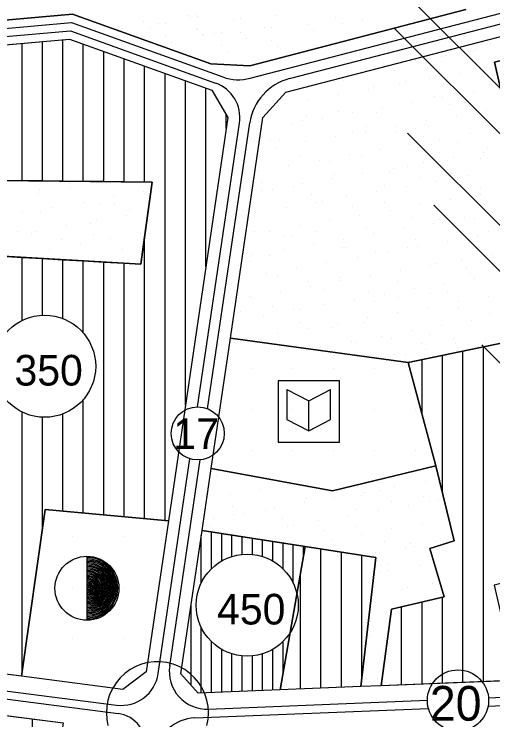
# Model space of a CAD drawing. Extents: x 419109 to 421295, y 4452223 to 4457798.
# Drawn here: x 420565 to 420799.4, y 4454402 to 4454747.5 of the extents above; entities that cross this region are included whole.
import ezdxf

# ---------------------------------------------------------------- set-up
doc = ezdxf.new("R2010")
doc.units = 0
for name, color, linetype in [('ADA', 7, 'Continuous'), ('ADAKENARI', 7, 'Continuous'), ('Default', 7, 'Continuous'), ('KALDIRIM', 7, 'Continuous'), ('KD_DAIRE', 7, 'Continuous'), ('KD_KAV_25', 7, 'Continuous'), ('KD_YGEN', 7, 'Continuous'), ('LJ_SEMBOL', 7, 'Continuous'), ('PL_AYA_PARK_DINLENME', 7, 'Continuous'), ('PL_K_YONETIM', 7, 'Continuous'), ('PL_KON_MEV_350', 7, 'Continuous'), ('PL_KON_MEV_450', 7, 'Continuous'), ('PL_SAY_KULTUR_TESIS', 7, 'Continuous'), ('SM_DAIRE', 7, 'Continuous'), ('SM_TAKS', 7, 'Continuous'), ('SN_TR_SIVILASMA', 7, 'Continuous'), ('TR_KULTURELTESIS', 7, 'Continuous'), ('TR_ORTAYOGUNKONUT', 7, 'Continuous'), ('TR_PARKALANI', 7, 'Continuous'), ('TR_YONETIMMERK', 7, 'Continuous'), ('TR_YUKSEKYOGUNKONUT', 7, 'Continuous')]:
    doc.layers.add(name, color=color, linetype=linetype)

# ---------------------------------------------------------------- blocks, each defined once
blk = doc.blocks.new('POINT_DISPLAY')
at = {"layer": 'Default'}
blk.add_line((0, 0), (0, 0), dxfattribs=at)

msp = doc.modelspace()

# ---------------------------------------------------------------- linework, layer by layer
at = {"layer": 'ADA'}
for p, q in [((420542.58, 4454666.29), (420632.64, 4454665.27)), ((420632.64, 4454665.27), (420627.04, 4454625.07)), ((420627.04, 4454625.07), (420548.18, 4454629.65)), ((420830.2, 4454592), (420757.98, 4454576.9)), ((420757.98, 4454576.9), (420670.89, 4454588.8)), ((420757.98, 4454576.9), (420771.44, 4454526.31)), ((420771.44, 4454526.31), (420720.85, 4454514.07)), ((420771.44, 4454526.31), (420780.42, 4454489.59)), ((420720.85, 4454514.07), (420661.49, 4454525.07)), ((420568.64, 4454423.32), (420580.23, 4454505)), ((420580.23, 4454505), (420640.51, 4454499.42)), ((420657.01, 4454494.75), (420707.55, 4454486.83)), ((420780.42, 4454489.59), (420768.59, 4454485.92)), ((420695.23, 4454416.69), (420707.55, 4454486.83)), ((420707.55, 4454486.83), (420742.07, 4454481.43)), ((420768.59, 4454485.92), (420775.52, 4454462.25)), ((420742.07, 4454481.43), (420734.72, 4454418.28)), ((420775.52, 4454462.25), (420749.82, 4454456.13)), ((420749.82, 4454456.13), (420744.73, 4454418.68))]:
    msp.add_line(p, q, dxfattribs=at)
at = {"layer": 'ADAKENARI'}
for p, q in [((420797.59, 4454735.13), (420945.3, 4454773.45)), ((420593.63, 4454747.49), (420456.15, 4454735.37)), ((420661.26, 4454723.14), (420593.63, 4454747.49)), ((420786.13, 4454749.72), (420680.35, 4454722.27)), ((420470.44, 4454724.58), (420592.05, 4454735.3)), ((420592.05, 4454735.3), (420661.73, 4454710.22)), ((420697.99, 4454709.28), (420797.59, 4454735.13)), ((420680.35, 4454722.27), (420661.26, 4454723.14)), ((420661.73, 4454710.22), (420669.68, 4454696.94)), ((420686.85, 4454696.88), (420697.99, 4454709.28)), ((420669.68, 4454696.94), (420640.51, 4454499.42)), ((420670.89, 4454588.8), (420686.85, 4454696.88)), ((420661.49, 4454525.07), (420670.89, 4454588.8)), ((420657.01, 4454494.75), (420661.49, 4454525.07)), ((420640.51, 4454499.42), (420629.6, 4454425.51)), ((420646.65, 4454424.56), (420657.01, 4454494.75)), ((420568.64, 4454423.32), (420472.42, 4454435.77)), ((420618.23, 4454416.9), (420568.64, 4454423.32)), ((420629.6, 4454425.51), (420618.23, 4454416.9)), ((420655.18, 4454415.07), (420646.65, 4454424.56)), ((420810.84, 4454421.35), (420744.73, 4454418.68)), ((420695.23, 4454416.69), (420655.18, 4454415.07)), ((420734.72, 4454418.28), (420695.23, 4454416.69)), ((420744.73, 4454418.68), (420734.72, 4454418.28)), ((420474.73, 4454415.3), (420589.01, 4454400.52))]:
    msp.add_line(p, q, dxfattribs=at)
at = {"layer": 'KALDIRIM'}
for p, q in [((420680.59, 4454716.13), (420830.76, 4454755.1)), ((420699.86, 4454715.97), (420832.6, 4454750.41)), ((420523.69, 4454737.3), (420593.1, 4454743.42)), ((420593.1, 4454743.42), (420667.23, 4454716.75)), ((420524.52, 4454733.36), (420592.58, 4454739.36)), ((420592.58, 4454739.36), (420663.61, 4454713.8)), ((420654.82, 4454555.24), (420675.34, 4454694.2)), ((420659.74, 4454554.3), (420680.41, 4454694.31)), ((420635.54, 4454424.63), (420651.07, 4454529.81)), ((420641.16, 4454428.46), (420656.04, 4454529.29)), ((420552.35, 4454417.36), (420615.19, 4454409.23)), ((420797.27, 4454412.79), (420882.86, 4454416.24)), ((420552.05, 4454413.37), (420615.88, 4454405.11)), ((420797.08, 4454408.78), (420897.74, 4454412.84)), ((420660.21, 4454407.27), (420767.32, 4454411.59)), ((420653.45, 4454403), (420767.84, 4454407.6))]:
    msp.add_line(p, q, dxfattribs=at)
for centre, radius, start, end in [((420674.9, 4454738.07), 22.66, 250.2061, 284.5462), ((420706.48, 4454690.46), 26.35, 104.5462, 171.6015), ((420657.51, 4454696.84), 18.03, 351.6015, 70.2061), ((420659.46, 4454425.76), 18.5, 171.6015, 272.3076), ((420617.53, 4454427.29), 18.21, 262.6284, 351.6015), ((420613.87, 4454389.57), 15.67, 350.7564, 82.6284), ((420654.27, 4454382.7), 20.31, 92.3076, 170.7564)]:
    msp.add_arc(centre, radius, start, end, dxfattribs=at)
at = {"layer": 'KD_DAIRE'}
for centre, radius in [((420654.88, 4454542.24), 13), ((420782.32, 4454411.49), 15)]:
    msp.add_circle(centre, radius, dxfattribs=at)
at = {"layer": 'KD_KAV_25'}
for p, q in [((420627.44, 4454429.25), (420624.52, 4454428.1)), ((420630.48, 4454430.03), (420627.44, 4454429.25)), ((420633.6, 4454430.43), (420630.48, 4454430.03)), ((420636.74, 4454430.43), (420633.6, 4454430.43)), ((420639.85, 4454430.03), (420636.74, 4454430.43)), ((420642.89, 4454429.25), (420639.85, 4454430.03)), ((420645.81, 4454428.1), (420642.89, 4454429.25)), ((420621.77, 4454426.59), (420619.23, 4454424.74)), ((420624.52, 4454428.1), (420621.77, 4454426.59)), ((420648.56, 4454426.59), (420645.81, 4454428.1)), ((420651.1, 4454424.74), (420648.56, 4454426.59)), ((420616.94, 4454422.59), (420614.94, 4454420.17)), ((420619.23, 4454424.74), (420616.94, 4454422.59)), ((420653.39, 4454422.59), (420651.1, 4454424.74)), ((420655.39, 4454420.17), (420653.39, 4454422.59)), ((420614.94, 4454420.17), (420613.26, 4454417.52)), ((420657.08, 4454417.52), (420655.39, 4454420.17)), ((420613.26, 4454417.52), (420611.92, 4454414.68)), ((420658.41, 4454414.68), (420657.08, 4454417.52)), ((420611.92, 4454414.68), (420610.95, 4454411.69)), ((420659.38, 4454411.69), (420658.41, 4454414.68)), ((420610.37, 4454408.61), (420610.17, 4454405.48)), ((420610.95, 4454411.69), (420610.37, 4454408.61)), ((420659.97, 4454408.61), (420659.38, 4454411.69)), ((420660.17, 4454405.48), (420659.97, 4454408.61)), ((420610.17, 4454405.48), (420610.37, 4454402.34)), ((420659.97, 4454402.34), (420660.17, 4454405.48)), ((420610.37, 4454402.34), (420610.95, 4454399.26)), ((420659.38, 4454399.26), (420659.97, 4454402.34))]:
    msp.add_line(p, q, dxfattribs=at)
at = {"layer": 'LJ_SEMBOL'}
for p, q in [((420694.23, 4454567.99), (420694.23, 4454537.99)), ((420724.23, 4454567.99), (420694.23, 4454567.99)), ((420724.23, 4454537.99), (420724.23, 4454567.99)), ((420698.54, 4454563.7), (420698.54, 4454549.04)), ((420698.54, 4454563.7), (420709.23, 4454558.26)), ((420709.23, 4454558.26), (420719.93, 4454563.7)), ((420719.93, 4454549.04), (420719.93, 4454563.7)), ((420709.23, 4454543.59), (420709.23, 4454558.26)), ((420698.54, 4454549.04), (420709.23, 4454543.59)), ((420709.23, 4454543.59), (420719.93, 4454549.04)), ((420694.23, 4454537.99), (420724.23, 4454537.99)), ((420600.67, 4454482.11), (420600.67, 4454450.78))]:
    msp.add_line(p, q, dxfattribs=at)
msp.add_lwpolyline([(420694.23, 4454537.99), (420724.23, 4454537.99), (420724.23, 4454567.99), (420694.23, 4454567.99)], close=True, dxfattribs=at)
msp.add_circle((420600.67, 4454466.44), 15.66, dxfattribs=at)
for radius in [15.04, 14.41, 13.78, 13.16, 12.53, 11.9, 11.28, 10.65, 10.02, 9.4, 8.77, 8.14, 7.52, 6.89, 6.26, 5.64, 5.01, 4.39, 3.76, 3.13, 2.51, 1.88, 1.25, 0.627]:
    msp.add_arc((420600.67, 4454466.44), radius, 270, 90, dxfattribs=at)
at = {"layer": 'PL_AYA_PARK_DINLENME'}
for p, q in [((420456.15, 4454735.37), (420593.63, 4454747.49)), ((420593.63, 4454747.49), (420661.26, 4454723.14)), ((420680.35, 4454722.27), (420786.13, 4454749.72)), ((420661.26, 4454723.14), (420680.35, 4454722.27))]:
    msp.add_line(p, q, dxfattribs=at)
for points in [[(420670.89, 4454588.8), (420686.85, 4454696.88), (420697.99, 4454709.28), (420797.59, 4454735.13), (420945.3, 4454773.45), (420957.64, 4454766.33), (420958.28, 4454764.04), (420877.7, 4454743.61), (420800.14, 4454723.93), (420830.2, 4454592), (420757.98, 4454576.9)], [(420720.85, 4454514.07), (420771.44, 4454526.31), (420780.42, 4454489.59), (420768.59, 4454485.92), (420775.52, 4454462.25), (420749.82, 4454456.13), (420744.73, 4454418.68), (420734.72, 4454418.28), (420742.07, 4454481.43), (420707.55, 4454486.83), (420657.01, 4454494.75), (420661.49, 4454525.07)]]:
    msp.add_lwpolyline(points, close=True, dxfattribs=at)
msp.add_lwpolyline([(420558.88, 4454629.03), (420568.88, 4454628.45), (420578.88, 4454627.87), (420588.88, 4454627.29), (420598.88, 4454626.71), (420608.88, 4454626.13), (420618.88, 4454625.55), (420627.04, 4454625.07), (420628.88, 4454638.25), (420632.64, 4454665.27), (420628.88, 4454665.31), (420618.88, 4454665.42), (420608.88, 4454665.54), (420598.88, 4454665.65), (420588.88, 4454665.76), (420578.88, 4454665.88), (420568.88, 4454665.99), (420558.88, 4454666.1)], dxfattribs=at)
at = {"layer": 'PL_K_YONETIM'}
msp.add_lwpolyline([(420568.64, 4454423.32), (420580.23, 4454505), (420640.51, 4454499.42), (420629.6, 4454425.51), (420618.23, 4454416.9)], close=True, dxfattribs=at)
at = {"layer": 'PL_KON_MEV_350'}
for points in [[(420963.16, 4454580.01), (420926.9, 4454562.62), (420936.73, 4454522.31), (420900.82, 4454443.93), (420873.04, 4454457.36), (420862.84, 4454454.91), (420856.72, 4454482.25), (420800.01, 4454467.97), (420810.84, 4454421.35), (420744.73, 4454418.68), (420749.82, 4454456.13), (420775.52, 4454462.25), (420768.59, 4454485.92), (420780.42, 4454489.59), (420771.44, 4454526.31), (420757.98, 4454576.9), (420830.2, 4454592), (420800.14, 4454723.93), (420877.7, 4454743.61), (420894.25, 4454682.17), (420974.23, 4454706.34), (420989.19, 4454652.27), (420987.69, 4454633.55)], [(420592.05, 4454735.3), (420661.73, 4454710.22), (420669.68, 4454696.94), (420640.51, 4454499.42), (420580.23, 4454505), (420568.64, 4454423.32), (420472.42, 4454435.77), (420472.69, 4454518.32), (420542.58, 4454516.19), (420541.97, 4454576.68), (420541.57, 4454616.93), (420548.18, 4454629.65), (420627.04, 4454625.07), (420632.64, 4454665.27), (420542.58, 4454666.29), (420534.98, 4454616.87), (420468.88, 4454616.18), (420470.44, 4454724.58)], [(420742.07, 4454481.43), (420734.72, 4454418.28), (420695.23, 4454416.69), (420707.55, 4454486.83)], [(420474.73, 4454415.3), (420589.01, 4454400.52), (420552.34, 4454145.16), (420575.43, 4454140.51), (420563.47, 4454057.09), (420525.18, 4454049.57), (420441.81, 4454052.61), (420443.29, 4454073.24), (420452.08, 4454141.13), (420509.8, 4454133.33), (420520.05, 4454189.39), (420424.05, 4454204.21), (420426.46, 4454230.76), (420449.87, 4454228.36), (420493.48, 4454293.72), (420534.29, 4454288.28), (420537.28, 4454311.95), (420497.84, 4454316.84), (420493.48, 4454293.72), (420449.87, 4454228.36)]]:
    msp.add_lwpolyline(points, close=True, dxfattribs=at)
at = {"layer": 'PL_KON_MEV_450'}
msp.add_lwpolyline([(420707.55, 4454486.83), (420695.23, 4454416.69), (420655.18, 4454415.07), (420646.65, 4454424.56), (420657.01, 4454494.75)], close=True, dxfattribs=at)
at = {"layer": 'PL_SAY_KULTUR_TESIS'}
msp.add_lwpolyline([(420720.85, 4454514.07), (420661.49, 4454525.07), (420670.89, 4454588.8), (420757.98, 4454576.9), (420771.44, 4454526.31)], close=True, dxfattribs=at)
at = {"layer": 'SM_DAIRE'}
for centre in [(420579.93, 4454575.13), (420679.12, 4454458.15)]:
    msp.add_circle(centre, 25, dxfattribs=at)
at = {"layer": 'SN_TR_SIVILASMA'}
for p, q in [((421258.65, 4454255.58), (420729.79, 4454784.44)), ((421258.42, 4454233.36), (420751.04, 4454740.73)), ((421257.96, 4454188.92), (420757.65, 4454689.23)), ((421257.73, 4454166.7), (420770.48, 4454653.95)), ((421257.26, 4454122.26), (420793.95, 4454585.57))]:
    msp.add_line(p, q, dxfattribs=at)
at = {"layer": 'TR_ORTAYOGUNKONUT'}
for p, q in [((420568.88, 4454665.99), (420568.88, 4454733.26)), ((420578.88, 4454665.88), (420578.88, 4454734.14)), ((420588.88, 4454665.76), (420588.88, 4454735.02)), ((420598.88, 4454665.65), (420598.88, 4454732.84)), ((420608.88, 4454665.54), (420608.88, 4454729.24)), ((420618.88, 4454665.42), (420618.88, 4454725.65)), ((420628.88, 4454665.31), (420628.88, 4454722.05)), ((420638.88, 4454499.57), (420638.88, 4454718.45)), ((420648.88, 4454556.06), (420648.88, 4454714.85)), ((420658.88, 4454623.79), (420658.88, 4454711.25)), ((420668.88, 4454691.53), (420668.88, 4454698.28)), ((420628.88, 4454500.5), (420628.88, 4454638.25)), ((420568.88, 4454597.55), (420568.88, 4454628.45)), ((420578.88, 4454600.1), (420578.88, 4454627.87)), ((420588.88, 4454598.47), (420588.88, 4454627.29)), ((420598.88, 4454591.43), (420598.88, 4454626.71)), ((420608.88, 4454502.35), (420608.88, 4454626.13)), ((420618.88, 4454501.42), (420618.88, 4454625.55)), ((420784.73, 4454420.3), (420784.73, 4454582.5)), ((420794.73, 4454420.7), (420794.73, 4454584.59)), ((420764.73, 4454551.53), (420764.73, 4454578.32)), ((420774.73, 4454512.85), (420774.73, 4454580.41)), ((420598.88, 4454503.27), (420598.88, 4454558.82)), ((420568.88, 4454424.98), (420568.88, 4454552.7)), ((420578.88, 4454495.44), (420578.88, 4454550.15)), ((420588.88, 4454504.2), (420588.88, 4454551.78)), ((420715.23, 4454417.49), (420715.23, 4454485.63)), ((420725.23, 4454417.9), (420725.23, 4454484.07)), ((420735.23, 4454422.69), (420735.23, 4454482.5)), ((420705.23, 4454417.09), (420705.23, 4454473.61)), ((420774.73, 4454419.89), (420774.73, 4454462.07)), ((420754.73, 4454419.09), (420754.73, 4454457.3)), ((420764.73, 4454419.49), (420764.73, 4454459.69)), ((420574.05, 4454320.38), (420574.05, 4454402.45))]:
    msp.add_line(p, q, dxfattribs=at)
at = {"layer": 'TR_YUKSEKYOGUNKONUT'}
for p, q in [((420656.65, 4454469.11), (420656.65, 4454492.3)), ((420661.65, 4454476.03), (420661.65, 4454494.02)), ((420666.65, 4454479.82), (420666.65, 4454493.24)), ((420671.65, 4454482.01), (420671.65, 4454492.46)), ((420676.65, 4454483.03), (420676.65, 4454491.67)), ((420681.65, 4454483.02), (420681.65, 4454490.89)), ((420686.65, 4454481.99), (420686.65, 4454490.11)), ((420691.65, 4454479.78), (420691.65, 4454489.33)), ((420696.65, 4454475.97), (420696.65, 4454488.54)), ((420701.65, 4454468.98), (420701.65, 4454487.76)), ((420706.65, 4454481.69), (420706.65, 4454486.98)), ((420651.65, 4454419), (420651.65, 4454458.43)), ((420656.65, 4454415.13), (420656.65, 4454447.18)), ((420661.65, 4454415.34), (420661.65, 4454440.26)), ((420696.65, 4454424.76), (420696.65, 4454440.33)), ((420666.65, 4454415.54), (420666.65, 4454436.48)), ((420691.65, 4454416.54), (420691.65, 4454436.52)), ((420671.65, 4454415.74), (420671.65, 4454434.29)), ((420676.65, 4454415.94), (420676.65, 4454433.27)), ((420681.65, 4454416.14), (420681.65, 4454433.28)), ((420686.65, 4454416.34), (420686.65, 4454434.31))]:
    msp.add_line(p, q, dxfattribs=at)

# ---------------------------------------------------------------- block references
at = {"layer": 'TR_KULTURELTESIS', "xscale": 0.1, "yscale": 0.10000000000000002}
for p in [(420681.49, 4454574.07), (420701.49, 4454574.07), (420721.49, 4454574.07), (420741.49, 4454574.07), (420681.49, 4454554.07), (420701.49, 4454554.07), (420721.49, 4454554.07), (420741.49, 4454554.07), (420761.49, 4454554.07), (420681.49, 4454534.07), (420701.49, 4454534.07), (420721.49, 4454534.07), (420741.49, 4454534.07), (420761.49, 4454534.07)]:
    msp.add_blockref('POINT_DISPLAY', p, dxfattribs=at)
at = {"layer": 'TR_PARKALANI', "xscale": 0.1, "yscale": 0.10000000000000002}
for p in [(420654.14, 4454747.12), (420628.5, 4454744.01), (420650.59, 4454746.7), (420651.25, 4454746.05), (420654.8, 4454746.47), (420672.29, 4454744.73), (420675.84, 4454745.15), (420693.42, 4454746.93), (420722.52, 4454745.98), (420735.49, 4454744.96), (420631.61, 4454741.01), (420635.47, 4454742.76), (420639.02, 4454743.18), (420654.14, 4454740.72), (420687.41, 4454740.79), (420690.96, 4454741.21), (420708.71, 4454742.69), (420725.63, 4454742.98), (420639.02, 4454736.77), (420654.8, 4454740.06), (420657.25, 4454737.72), (420657.91, 4454737.07), (420663.09, 4454738.16), (420666.64, 4454738.58), (420675.84, 4454738.75), (420711.82, 4454739.7), (420642.13, 4454733.78), (420678.95, 4454735.75), (420690.96, 4454734.8), (420798.47, 4454733.37), (420666.63, 4454732.17), (420694.07, 4454731.81), (420791.12, 4454730.11), (420669.75, 4454729.18), (420774.07, 4454726.75), (420776.35, 4454727.5), (420789.71, 4454729.07), (420761.57, 4454724.9), (420786.98, 4454723.73), (420751.14, 4454719.77), (420797.78, 4454721.13), (420783.01, 4454718.52), (420726.28, 4454714.87), (420753.46, 4454713.31), (420756.69, 4454714.59), (420768.23, 4454715.92), (420738.69, 4454710.71), (420741.05, 4454712.27), (420789.67, 4454709.54), (420723.92, 4454708.11), (420770.59, 4454707.06), (420774.89, 4454706.94), (420694.37, 4454702.9), (420709.15, 4454705.5), (420760.12, 4454704.33), (420778.08, 4454703.22), (420785.37, 4454704.45), (420693.26, 4454700.39), (420723.67, 4454700.1), (420730.58, 4454699.13), (420742.25, 4454699.25), (420745.35, 4454701.73), (420796.33, 4454700.56), (420706.41, 4454695.29), (420708.03, 4454697.78), (420715.81, 4454696.52), (420766.78, 4454695.35), (420781.56, 4454697.96), (420701.03, 4454693.92), (420737.58, 4454692.57), (420752.01, 4454692.75), (420766.59, 4454693.57), (420767.99, 4454692.29), (420686.26, 4454691.31), (420730.76, 4454689.61), (420737.24, 4454690.15), (420752.35, 4454689.97), (420788.22, 4454688.98), (420690.65, 4454685.61), (420694.92, 4454685.65), (420707.69, 4454684.94), (420722.47, 4454687.54), (420773.44, 4454686.37), (420692.92, 4454682.33), (420758.67, 4454683.77), (420781.89, 4454684.76), (420796.66, 4454682.15), (420704.56, 4454678.08), (420729.13, 4454678.56), (420743.9, 4454681.17), (420794.88, 4454680), (420714.36, 4454675.96), (420719.33, 4454675.48), (420734.97, 4454677.8), (420765.33, 4454674.79), (420780.1, 4454677.4), (420793.54, 4454677.02), (420699.58, 4454673.35), (420750.56, 4454672.19), (420757.7, 4454673.06), (420684.81, 4454670.75), (420721.86, 4454669.09), (420735.79, 4454669.58), (420748.88, 4454670.27), (420763.65, 4454667.67), (420779.29, 4454669.98), (420786.76, 4454668.42), (420592.09, 4454664.42), (420686.03, 4454665.13), (420706.24, 4454664.37), (420721.02, 4454666.98), (420771.99, 4454665.81), (420782.05, 4454667.38), (420577.32, 4454661.82), (420592.72, 4454661.95), (420628.29, 4454660.65), (420686.31, 4454660.99), (420691.47, 4454661.77), (420701.95, 4454663.31), (420746.21, 4454663.42), (420757.22, 4454663.21), (420793.19, 4454662.46), (420577.08, 4454659.63), (420613.52, 4454658.05), (420710.37, 4454659.45), (420727.68, 4454658), (420742.45, 4454660.6), (420793.43, 4454659.44), (420598.75, 4454655.44), (420606.63, 4454654.42), (420613.95, 4454654.56), (420712.9, 4454655.39), (420715.86, 4454655.78), (420746.27, 4454655.5), (420763.88, 4454654.23), (420778.65, 4454656.83), (420578.11, 4454650.6), (420583.98, 4454652.84), (420621.4, 4454651.81), (420698.13, 4454652.79), (420730.63, 4454653.18), (420749.11, 4454651.62), (420569.21, 4454650.23), (420620.18, 4454649.07), (420683.36, 4454650.18), (420734.34, 4454649.02), (420760.17, 4454647.97), (420773.15, 4454646.86), (420785.31, 4454647.85), (420790.59, 4454647.68), (420590.64, 4454643.86), (420602.46, 4454644.92), (420605.41, 4454646.46), (420704.79, 4454643.81), (420719.56, 4454646.41), (420770.54, 4454645.25), (420774.95, 4454645.36), (420566.62, 4454640.96), (420573.61, 4454639.93), (420575.87, 4454641.25), (420626.84, 4454640.09), (420682.84, 4454641.3), (420690.02, 4454641.2), (420713.25, 4454641.01), (420737.32, 4454642.9), (420741, 4454640.04), (420755.77, 4454642.64), (420797.5, 4454641.18), (420588.38, 4454637.33), (420604.02, 4454639.65), (420612.07, 4454637.48), (420697.61, 4454638.69), (420701.48, 4454638.94), (420726.22, 4454637.43), (420761.66, 4454637.22), (420791.97, 4454638.87), (420597.3, 4454634.88), (420711.45, 4454634.83), (420725.83, 4454633.26), (420727.16, 4454633.48), (420757.57, 4454633.2), (420762.43, 4454633.66), (420777.2, 4454636.27), (420567.75, 4454629.67), (420582.53, 4454632.27), (420617.93, 4454632.12), (420681.91, 4454629.62), (420696.68, 4454632.22), (420741.93, 4454630.88), (420747.66, 4454631.06), (420798.63, 4454629.89), (420618.73, 4454628.5), (420680.24, 4454626.52), (420689.99, 4454629.3), (420732.89, 4454628.45), (420783.86, 4454627.29), (420703.34, 4454623.24), (420718.11, 4454625.85), (420769.09, 4454624.68), (420771.47, 4454625.67), (420786.25, 4454623.06), (420688.57, 4454620.64), (420739.55, 4454619.47), (420754.32, 4454622.08), (420788.61, 4454620.67), (420694.14, 4454619), (420708.91, 4454616.39), (420724.55, 4454618.71), (420724.77, 4454616.87), (420752.77, 4454616.7), (420790.52, 4454618.31), (420710, 4454614.26), (420716.93, 4454612.74), (420760.98, 4454613.1), (420775.75, 4454615.7), (420680.46, 4454609.05), (420695.23, 4454611.66), (420738.46, 4454611.18), (420746.21, 4454610.49), (420768.87, 4454610.9), (420777.12, 4454611.03), (420797.18, 4454609.33), (420681.1, 4454608.78), (420731.43, 4454607.89), (420741.28, 4454607.06), (420753.23, 4454608.58), (420782.41, 4454606.72), (420675.89, 4454601.9), (420691.54, 4454604.22), (420701.89, 4454602.68), (420705.44, 4454603.1), (420716.66, 4454605.28), (420767.64, 4454604.12), (420782.77, 4454603.37), (420687.12, 4454600.07), (420738.09, 4454598.91), (420752.87, 4454601.51), (420797.54, 4454600.76), (420672.35, 4454597.47), (420705.44, 4454596.7), (420723.32, 4454596.3), (420735.85, 4454596.41), (420774.3, 4454595.14), (420789.07, 4454597.74), (420708.55, 4454593.7), (420720.21, 4454594.09), (420759.53, 4454592.53), (420679.01, 4454588.49), (420693.78, 4454591.09), (420744.76, 4454589.93), (420749.76, 4454588.88), (420768.22, 4454590.51), (420780.17, 4454588.6), (420795.73, 4454588.76), (420715.21, 4454584.72), (420729.98, 4454587.32), (420732.39, 4454586.55), (420764.53, 4454586.28), (420780.96, 4454586.16), (420792.57, 4454584.83), (420766.19, 4454583.55), (420751.42, 4454580.95), (420756.73, 4454580.87), (420664.26, 4454521.1), (420690.67, 4454519.46), (420700.47, 4454517.33), (420705.45, 4454516.85), (420751.45, 4454516.17), (420766.22, 4454518.77), (420670.93, 4454512.12), (420685.7, 4454514.73), (420736.67, 4454513.56), (420743.81, 4454514.43), (420707.98, 4454510.47), (420721.9, 4454510.96), (420734.99, 4454511.65), (420749.76, 4454509.04), (420765.4, 4454511.36), (420768.16, 4454508.75), (420772.88, 4454509.79), (420672.14, 4454506.51), (420692.36, 4454505.75), (420707.13, 4454508.35), (420758.11, 4454507.19), (420672.43, 4454502.37), (420677.59, 4454503.14), (420688.07, 4454504.69), (420728.56, 4454501.98), (420732.32, 4454504.79), (420743.33, 4454504.58), (420662.81, 4454500.54), (420696.49, 4454500.83), (420713.79, 4454499.37), (420660.65, 4454496.87), (420699.02, 4454496.77), (420701.97, 4454497.16), (420732.38, 4454496.87), (420750, 4454495.6), (420764.77, 4454498.21), (420684.25, 4454494.16), (420716.74, 4454494.55), (420735.22, 4454493), (420720.45, 4454490.39), (420746.29, 4454489.34), (420759.27, 4454488.24), (420771.43, 4454489.23), (420776.7, 4454489.06), (420705.68, 4454487.79), (420756.66, 4454486.62), (420761.06, 4454486.74), (420741.88, 4454484.02), (420747.78, 4454478.6), (420763.32, 4454477.64), (420743.68, 4454474.57), (420748.54, 4454475.04), (420769.98, 4454468.66), (420755.2, 4454466.06), (420757.59, 4454467.04), (420772.36, 4454464.44), (420740.43, 4454463.45), (420747.09, 4454454.47), (420739.34, 4454449.95), (420738.98, 4454442.89), (420745.64, 4454433.91), (420737.53, 4454422.32), (420742.85, 4454422.24)]:
    msp.add_blockref('POINT_DISPLAY', p, dxfattribs=at)
at = {"layer": 'TR_YONETIMMERK', "xscale": 0.1, "yscale": 0.10000000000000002}
for p in [(420593.64, 4454491.9), (420618.64, 4454491.9), (420593.64, 4454466.9), (420618.64, 4454466.9), (420593.64, 4454441.9), (420618.64, 4454441.9)]:
    msp.add_blockref('POINT_DISPLAY', p, dxfattribs=at)

# ---------------------------------------------------------------- texts
at = {"layer": 'KD_YGEN'}
for s, height, p in [('17', 15, (420642.96, 4454534.62)), ('20', 17, (420768.56, 4454401.6))]:
    msp.add_text(s, height=height, dxfattribs=at).set_placement(p)
at = {"layer": 'SM_TAKS'}
for s, p in [('350', (420565.18, 4454565.68)), ('450', (420664.37, 4454448.7))]:
    msp.add_text(s, height=15, dxfattribs=at).set_placement(p)

doc.saveas('drawing.dxf')
